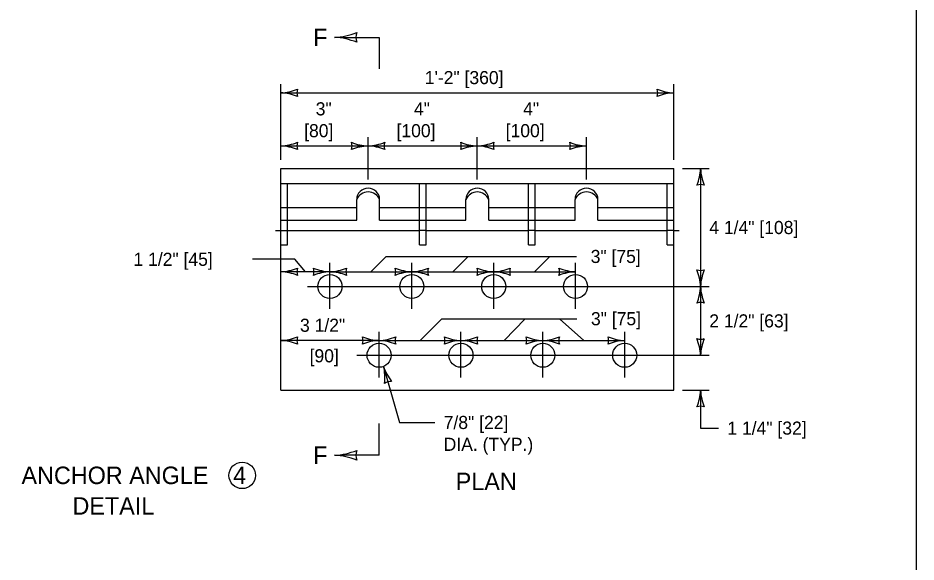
# Model space of a CAD drawing. Extents: x 49991.4 to 50021, y 49987.6 to 50011.4.
# Drawn here: x 50012.637 to 50016.75, y 49994.106 to 49996.597 of the extents above; entities that cross this region are included whole.
import ezdxf

# ---------------------------------------------------------------- set-up
doc = ezdxf.new("R2010")
doc.units = 0
for name, color, linetype in [('Level 1', 7, 'Continuous'), ('Level 2', 7, 'Continuous'), ('Level 3', 7, 'Continuous'), ('Level 4', 7, 'Continuous'), ('Level 5', 7, 'Continuous'), ('Level 6', 7, 'Continuous')]:
    doc.layers.add(name, color=color, linetype=linetype)

msp = doc.modelspace()

# ---------------------------------------------------------------- linework, layer by layer
at = {"layer": 'Level 1'}
for p, q in [((50013.8406, 49994.8924), (50013.8406, 49995.9074)), ((50013.8406, 49995.9074), (50015.6406, 49995.9074)), ((50015.6406, 49994.8924), (50015.6406, 49995.9074)), ((50014.1881, 49995.6709), (50014.1881, 49995.765)), ((50014.2931, 49995.6709), (50014.2931, 49995.765)), ((50014.6881, 49995.6709), (50014.6881, 49995.765)), ((50014.7931, 49995.6709), (50014.7931, 49995.765)), ((50015.1881, 49995.6709), (50015.1881, 49995.765)), ((50015.2931, 49995.6709), (50015.2931, 49995.765)), ((50013.8406, 49995.7294), (50014.1881, 49995.7294)), ((50014.2931, 49995.7294), (50014.6881, 49995.7294)), ((50014.7931, 49995.7294), (50015.1881, 49995.7294)), ((50015.2931, 49995.7294), (50015.6406, 49995.7294)), ((50013.8406, 49995.6709), (50014.1881, 49995.6709)), ((50013.8706, 49995.5586), (50013.8706, 49995.6709)), ((50014.2931, 49995.6709), (50014.6881, 49995.6709)), ((50014.4756, 49995.5586), (50014.4756, 49995.6709)), ((50014.5056, 49995.5586), (50014.5056, 49995.6709)), ((50014.7931, 49995.6709), (50015.1881, 49995.6709)), ((50014.9756, 49995.5586), (50014.9756, 49995.6709)), ((50015.0056, 49995.5586), (50015.0056, 49995.6709)), ((50015.2931, 49995.6709), (50015.6406, 49995.6709)), ((50015.6106, 49995.5586), (50015.6106, 49995.6709)), ((50013.8156, 49995.6236), (50013.8406, 49995.6236)), ((50013.8706, 49995.6236), (50014.4756, 49995.6236)), ((50014.5056, 49995.6236), (50014.9756, 49995.6236)), ((50015.0056, 49995.6236), (50015.6106, 49995.6236)), ((50015.6406, 49995.6236), (50015.6656, 49995.6236)), ((50013.8406, 49995.5586), (50013.8706, 49995.5586)), ((50014.4756, 49995.5586), (50014.5056, 49995.5586)), ((50014.9756, 49995.5586), (50015.0056, 49995.5586)), ((50015.6106, 49995.5586), (50015.6406, 49995.5586)), ((50013.8406, 49994.8924), (50015.6406, 49994.8924))]:
    msp.add_line(p, q, dxfattribs=at)
msp.add_lwpolyline([(49999.3835, 49998.9992), (50016.7501, 49998.9992), (50016.7501, 49987.7988), (49999.3835, 49987.7988)], close=True, dxfattribs=at)
for centre in [(50014.0656, 49995.3674), (50014.4406, 49995.3674), (50014.8156, 49995.3674), (50015.1906, 49995.3674), (50014.2906, 49995.0524), (50014.6656, 49995.0524), (50015.0406, 49995.0524), (50015.4156, 49995.0524)]:
    msp.add_circle(centre, 0.055, dxfattribs=at)
for centre, radius, start, end in [((50014.2406, 49995.765), 0.0525, 90, 180), ((50014.2406, 49995.7431), 0.0569, 22.6199, 157.3801), ((50014.2406, 49995.765), 0.0525, 0, 90), ((50014.7406, 49995.765), 0.0525, 90, 180), ((50014.7406, 49995.7431), 0.0569, 22.6199, 157.3801), ((50014.7406, 49995.765), 0.0525, 0, 90), ((50015.2406, 49995.765), 0.0525, 90, 180), ((50015.2406, 49995.7431), 0.0569, 22.6199, 157.3801), ((50015.2406, 49995.765), 0.0525, 0, 90)]:
    msp.add_arc(centre, radius, start, end, dxfattribs=at)
at = {"layer": 'Level 2'}
msp.add_circle((50013.6638, 49994.5026), 0.0608, dxfattribs=at)
at = {"layer": 'Level 3'}
for p, q in [((50013.8406, 49995.9474), (50013.8406, 49996.2939)), ((50015.6406, 49995.9474), (50015.6406, 49996.2939)), ((50013.8406, 49996.2539), (50015.6406, 49996.2539)), ((50014.2406, 49995.8575), (50014.2406, 49996.0508)), ((50014.7406, 49995.8575), (50014.7406, 49996.0508)), ((50015.2406, 49995.8575), (50015.2406, 49996.0508)), ((50013.8406, 49996.0108), (50014.2406, 49996.0108)), ((50014.2406, 49996.0108), (50014.7406, 49996.0108)), ((50014.7406, 49996.0108), (50015.2406, 49996.0108)), ((50015.6806, 49995.9074), (50015.8031, 49995.9074)), ((50015.7631, 49995.9074), (50015.7631, 49995.3674)), ((50014.2531, 49995.4349), (50014.3231, 49995.5049)), ((50014.3231, 49995.5049), (50015.1956, 49995.5049)), ((50014.6281, 49995.4349), (50014.6981, 49995.5049)), ((50015.0031, 49995.4349), (50015.0731, 49995.5049)), ((50014.0656, 49995.4349), (50013.8406, 49995.4349)), ((50014.0656, 49995.4349), (50014.4406, 49995.4349)), ((50014.4406, 49995.4349), (50014.8156, 49995.4349)), ((50014.8156, 49995.4349), (50015.1906, 49995.4349)), ((50015.7631, 49995.3674), (50015.7631, 49995.0524)), ((50014.9595, 49995.2199), (50014.8632, 49995.1199)), ((50015.2281, 49995.1199), (50015.1174, 49995.2199)), ((50014.2906, 49995.1199), (50013.8406, 49995.1199)), ((50014.2906, 49995.1199), (50014.6656, 49995.1199)), ((50014.6656, 49995.1199), (50015.0406, 49995.1199)), ((50015.0406, 49995.1199), (50015.4156, 49995.1199)), ((50014.3111, 49995.0013), (50014.3842, 49994.7448)), ((50015.6806, 49994.8924), (50015.8031, 49994.8924)), ((50015.7631, 49994.8924), (50015.7631, 49994.7189)), ((50014.3842, 49994.7448), (50014.5466, 49994.7448)), ((50015.7631, 49994.7189), (50015.8459, 49994.7189))]:
    msp.add_line(p, q, dxfattribs=at)
for points in [[(50013.9531, 49995.4349), (50013.9041, 49995.4919), (50013.7102, 49995.4919)], [(50014.4781, 49995.1199), (50014.5781, 49995.2199), (50015.1968, 49995.2199)]]:
    msp.add_lwpolyline(points, dxfattribs=at)
for centre, radius, start, end in [((50013.8291, 49996.4867), 0.233, 272.8273, 292.0772), ((50013.8314, 49996.0318), 0.2223, 67.456, 87.6395), ((50013.9688, 49996.2539), 0.0548, 162.1388, 197.8612), ((50015.6497, 49996.4761), 0.2223, 247.456, 267.6395), ((50015.5124, 49996.2539), 0.0548, 342.1388, 17.8612), ((50015.6521, 49996.0212), 0.233, 92.8273, 112.0772), ((50013.8291, 49996.2435), 0.233, 272.8273, 292.0772), ((50013.8314, 49995.7887), 0.2223, 67.456, 87.6395), ((50013.9688, 49996.0108), 0.0548, 162.1388, 197.8612), ((50014.2497, 49996.2329), 0.2223, 247.456, 267.6395), ((50014.1124, 49996.0108), 0.0548, 342.1388, 17.8612), ((50014.2521, 49995.7781), 0.233, 92.8273, 112.0772), ((50014.2291, 49996.2435), 0.233, 272.8273, 292.0772), ((50014.2314, 49995.7887), 0.2223, 67.456, 87.6395), ((50014.3688, 49996.0108), 0.0548, 162.1388, 197.8612), ((50014.7497, 49996.2329), 0.2223, 247.456, 267.6395), ((50014.6124, 49996.0108), 0.0548, 342.1388, 17.8612), ((50014.7521, 49995.7781), 0.233, 92.8273, 112.0772), ((50014.7291, 49996.2435), 0.233, 272.8273, 292.0772), ((50014.7314, 49995.7887), 0.2223, 67.456, 87.6395), ((50014.8688, 49996.0108), 0.0548, 162.1388, 197.8612), ((50015.2497, 49996.2329), 0.2223, 247.456, 267.6395), ((50015.1124, 49996.0108), 0.0548, 342.1388, 17.8612), ((50015.2521, 49995.7781), 0.233, 92.8273, 112.0772), ((50015.541, 49995.9165), 0.2223, 337.456, 357.6395), ((50015.9958, 49995.9189), 0.233, 182.8273, 202.0772), ((50015.7631, 49995.7792), 0.0548, 72.1388, 107.8612), ((50013.8291, 49995.6676), 0.233, 272.8273, 292.0772), ((50013.8314, 49995.2127), 0.2223, 67.456, 87.6395), ((50013.9688, 49995.4349), 0.0548, 162.1388, 197.8612), ((50014.0747, 49995.657), 0.2223, 247.456, 267.6395), ((50013.9374, 49995.4349), 0.0548, 342.1388, 17.8612), ((50014.0771, 49995.2022), 0.233, 92.8273, 112.0772), ((50014.0541, 49995.6676), 0.233, 272.8273, 292.0772), ((50014.0564, 49995.2127), 0.2223, 67.456, 87.6395), ((50014.1938, 49995.4349), 0.0548, 162.1388, 197.8612), ((50014.4497, 49995.657), 0.2223, 247.456, 267.6395), ((50014.3124, 49995.4349), 0.0548, 342.1388, 17.8612), ((50014.4521, 49995.2022), 0.233, 92.8273, 112.0772), ((50014.4291, 49995.6676), 0.233, 272.8273, 292.0772), ((50014.4314, 49995.2127), 0.2223, 67.456, 87.6395), ((50014.5688, 49995.4349), 0.0548, 162.1388, 197.8612), ((50014.8247, 49995.657), 0.2223, 247.456, 267.6395), ((50014.6874, 49995.4349), 0.0548, 342.1388, 17.8612), ((50014.8271, 49995.2022), 0.233, 92.8273, 112.0772), ((50014.8041, 49995.6676), 0.233, 272.8273, 292.0772), ((50014.8064, 49995.2127), 0.2223, 67.456, 87.6395), ((50014.9438, 49995.4349), 0.0548, 162.1388, 197.8612), ((50015.1997, 49995.657), 0.2223, 247.456, 267.6395), ((50015.0624, 49995.4349), 0.0548, 342.1388, 17.8612), ((50015.2021, 49995.2022), 0.233, 92.8273, 112.0772), ((50015.7631, 49995.4956), 0.0548, 252.1388, 287.8612), ((50015.5304, 49995.3559), 0.233, 2.8273, 22.0772), ((50015.9853, 49995.3582), 0.2223, 157.456, 177.6395), ((50015.541, 49995.3765), 0.2223, 337.456, 357.6395), ((50015.9958, 49995.3789), 0.233, 182.8273, 202.0772), ((50015.7631, 49995.2392), 0.0548, 72.1388, 107.8612), ((50013.8291, 49995.3526), 0.233, 272.8273, 292.0772), ((50013.9688, 49995.1199), 0.0548, 162.1388, 197.8612), ((50014.2997, 49995.342), 0.2223, 247.456, 267.6395), ((50014.1624, 49995.1199), 0.0548, 342.1388, 17.8612), ((50014.2791, 49995.3526), 0.233, 272.8273, 292.0772), ((50014.4188, 49995.1199), 0.0548, 162.1388, 197.8612), ((50014.6747, 49995.342), 0.2223, 247.456, 267.6395), ((50014.5374, 49995.1199), 0.0548, 342.1388, 17.8612), ((50014.6541, 49995.3526), 0.233, 272.8273, 292.0772), ((50014.7938, 49995.1199), 0.0548, 162.1388, 197.8612), ((50015.0497, 49995.342), 0.2223, 247.456, 267.6395), ((50014.9124, 49995.1199), 0.0548, 342.1388, 17.8612), ((50015.0291, 49995.3526), 0.233, 272.8273, 292.0772), ((50015.1688, 49995.1199), 0.0548, 162.1388, 197.8612), ((50015.4247, 49995.342), 0.2223, 247.456, 267.6395), ((50015.2874, 49995.1199), 0.0548, 342.1388, 17.8612), ((50013.8314, 49994.8977), 0.2223, 67.456, 87.6395), ((50014.3021, 49994.8872), 0.233, 92.8273, 112.0772), ((50014.2814, 49994.8977), 0.2223, 67.456, 87.6395), ((50014.6771, 49994.8872), 0.233, 92.8273, 112.0772), ((50014.6564, 49994.8977), 0.2223, 67.456, 87.6395), ((50015.0521, 49994.8872), 0.233, 92.8273, 112.0772), ((50015.0314, 49994.8977), 0.2223, 67.456, 87.6395), ((50015.4271, 49994.8872), 0.233, 92.8273, 112.0772), ((50015.7631, 49995.1806), 0.0548, 252.1388, 287.8612), ((50015.5304, 49995.0409), 0.233, 2.8273, 22.0772), ((50015.9853, 49995.0432), 0.2223, 157.456, 177.6395), ((50014.095, 49994.9493), 0.2223, 353.3508, 13.5343), ((50014.5318, 49995.0761), 0.233, 198.7221, 217.972), ((50014.3462, 49994.878), 0.0548, 88.0336, 123.756), ((50015.541, 49994.9015), 0.2223, 337.456, 357.6395), ((50015.9958, 49994.9039), 0.233, 182.8273, 202.0772), ((50015.7631, 49994.7642), 0.0548, 72.1388, 107.8612)]:
    msp.add_arc(centre, radius, start, end, dxfattribs=at)
at = {"layer": 'Level 4'}
for p, q in [((50013.8406, 49995.8389), (50015.6406, 49995.8389)), ((50013.8706, 49995.6709), (50013.8706, 49995.8389)), ((50014.4756, 49995.6709), (50014.4756, 49995.8389)), ((50014.5056, 49995.6709), (50014.5056, 49995.8389)), ((50014.9756, 49995.6709), (50014.9756, 49995.8389)), ((50015.0056, 49995.6709), (50015.0056, 49995.8389)), ((50015.6106, 49995.6709), (50015.6106, 49995.8389)), ((50013.8406, 49995.6236), (50013.8706, 49995.6236)), ((50014.5056, 49995.6236), (50014.4756, 49995.6236)), ((50015.0056, 49995.6236), (50014.9756, 49995.6236)), ((50015.6406, 49995.6236), (50015.6106, 49995.6236))]:
    msp.add_line(p, q, dxfattribs=at)
at = {"layer": 'Level 5'}
for p, q in [((50014.0656, 49995.2649), (50014.0656, 49995.4749)), ((50014.4406, 49995.2649), (50014.4406, 49995.4749)), ((50014.8156, 49995.2649), (50014.8156, 49995.4749)), ((50015.1906, 49995.2649), (50015.1906, 49995.4749)), ((50013.9631, 49995.3674), (50015.8031, 49995.3674)), ((50014.2906, 49994.9499), (50014.2906, 49995.1599)), ((50014.6656, 49994.9499), (50014.6656, 49995.1599)), ((50015.0406, 49994.9499), (50015.0406, 49995.1599)), ((50015.4156, 49994.9499), (50015.4156, 49995.1599)), ((50014.1881, 49995.0524), (50015.8031, 49995.0524))]:
    msp.add_line(p, q, dxfattribs=at)
at = {"layer": 'Level 6'}
for p, q in [((50014.1119, 49996.5079), (50014.2906, 49996.5079)), ((50014.2906, 49996.5079), (50014.2906, 49996.3639)), ((50014.2906, 49994.5947), (50014.2906, 49994.7394)), ((50014.2906, 49994.5947), (50014.1119, 49994.5947))]:
    msp.add_line(p, q, dxfattribs=at)
for centre, radius, start, end in [((50014.0713, 49996.8182), 0.3107, 272.8273, 292.0772), ((50014.0744, 49996.2117), 0.2964, 67.456, 87.6395), ((50014.2576, 49996.5079), 0.073, 162.1388, 197.8612), ((50014.0713, 49994.905), 0.3107, 272.8273, 292.0772), ((50014.2576, 49994.5947), 0.073, 162.1388, 197.8612), ((50014.0744, 49994.2985), 0.2964, 67.456, 87.6395)]:
    msp.add_arc(centre, radius, start, end, dxfattribs=at)

# ---------------------------------------------------------------- texts
at = {"layer": 'Level 2'}
for s, height, p in [('F', 0.08, (50013.9887, 49996.4679)), ('1\'-2" [360]', 0.06, (50014.5, 49996.2939)), ('3"', 0.06, (50014.0004, 49996.1508)), ('4"', 0.06, (50014.4504, 49996.1508)), ('4"', 0.06, (50014.9504, 49996.1508)), ('[80]', 0.06, (50013.9474, 49996.0508)), ('[100]', 0.06, (50014.3705, 49996.0508)), ('[100]', 0.06, (50014.8705, 49996.0508)), ('4 1/4" [108]', 0.06, (50015.8031, 49995.6074)), ('1 1/2" [45]', 0.06, (50013.1657, 49995.4619)), ('3" [75]', 0.06, (50015.2598, 49995.4749)), ('3 1/2"', 0.06, (50013.9285, 49995.1599)), ('3" [75]', 0.06, (50015.2611, 49995.1899)), ('2 1/2" [63]', 0.06, (50015.8031, 49995.1799)), ('[90]', 0.06, (50013.9723, 49995.0199)), ('7/8" [22]', 0.06, (50014.5866, 49994.7148)), ('1 1/4" [32]', 0.06, (50015.8859, 49994.6889)), ('DIA. (TYP.)', 0.06, (50014.5866, 49994.6148)), ('F', 0.08, (50013.9887, 49994.5547)), ('ANCHOR ANGLE', 0.08, (50012.6528, 49994.4626)), ('4', 0.08, (50013.6223, 49994.4627)), ('PLAN', 0.08, (50014.6417, 49994.4348)), ('DETAIL', 0.08, (50012.8864, 49994.3226))]:
    msp.add_text(s, height=height, dxfattribs=at).set_placement(p)

doc.saveas('drawing.dxf')
